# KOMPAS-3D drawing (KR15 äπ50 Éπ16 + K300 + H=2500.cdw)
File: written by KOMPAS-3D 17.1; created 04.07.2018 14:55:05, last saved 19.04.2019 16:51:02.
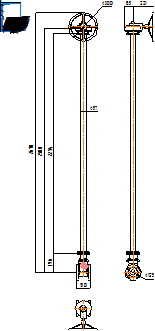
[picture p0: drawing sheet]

Sheet 1: A4, portrait

Title block, sheet 1: name: KR15 Ду50 Ру16 + / K300 + H=2500; material: Внимание! Данный продукт является объектом авторского права ООО «Торговый Дом АДЛ». / Запрещается изменение, копирование, распространение / (в том числе путем копирования на другие сайты и ресурсы в Интернете) / или любое иное использование информации и объектов без предварительного / согласия правообладателя (ООО «Торговый Дом АДЛ»).; mass: 36,7; sheets: 1; organisation: ООО "Торговый дом АДЛ"; sheet format: A4; stored path: \\adlc.lan\data\АДЛ_ПКД\3D-модели\ADL production\Клиновые задвижки серии KR ГРАНАР\Клиновые задвижки KR15 со стационарным удлинением\KOMPAS 2D\KR15 Ду50 Ру16 + K300 + H=2500.cdw

Views: Вид 1, Проекционный вид 3
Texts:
  kka
  adl
Dimensions and other numbers on the sheet: 2500; 2254; 150; 2670; 300; 221; 85; 57; 125; 196; 1:1; 1; 36,7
